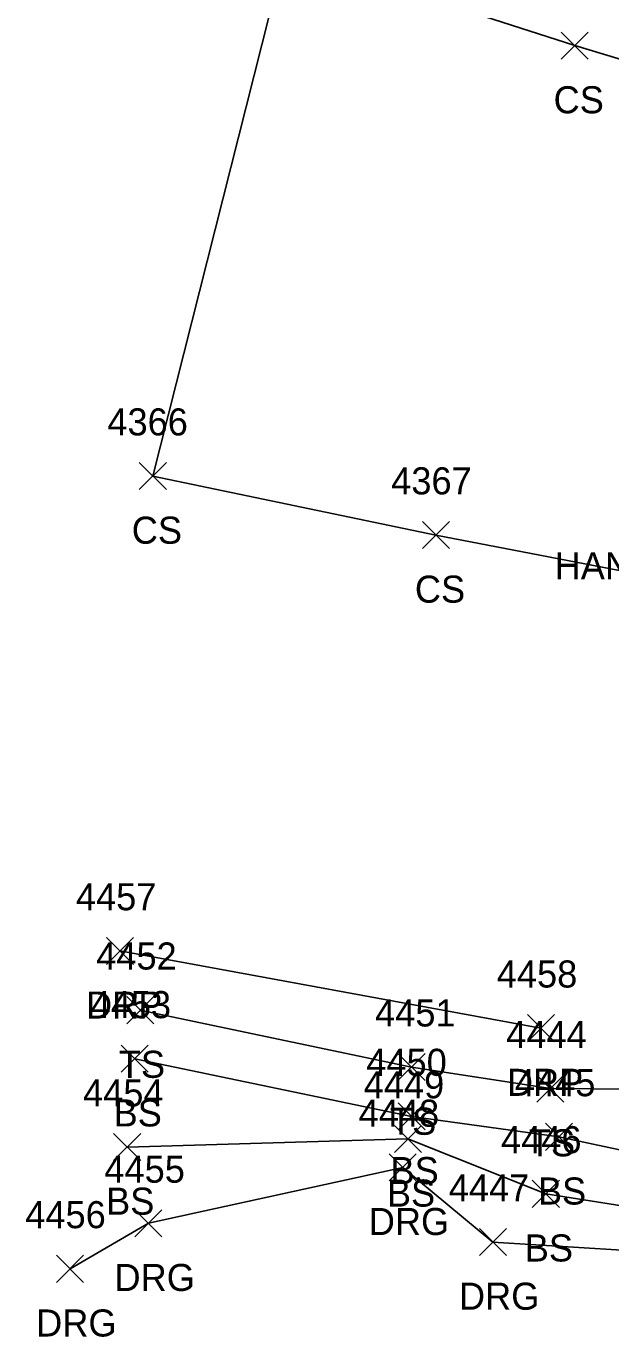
# Model space of a CAD drawing. Extents: x 1443912 to 1445411, y 621446 to 623693.
# Drawn here: x 1444840.5 to 1444883.7, y 623239.1 to 623335.6 of the extents above; entities that cross this region are included whole.
import ezdxf

# ---------------------------------------------------------------- set-up
doc = ezdxf.new("R2010")
doc.units = 0
for name, color, linetype in [('L_A', 7, 'Continuous'), ('L_I', 7, 'Continuous'), ('L_TIC', 7, 'Continuous'), ('LELB', 7, 'Continuous'), ('R_A', 7, 'Continuous'), ('R_I', 7, 'Continuous'), ('R_TIC', 7, 'Continuous'), ('RDG', 7, 'Continuous'), ('RDP', 7, 'Continuous'), ('S_C', 7, 'Continuous')]:
    doc.layers.add(name, color=color, linetype=linetype)

msp = doc.modelspace()

# ---------------------------------------------------------------- linework, layer by layer
at = {"layer": 'L_TIC'}
for points in [[(1444880.011, 623333.123), (1444882.011, 623335.123)], [(1444882.011, 623333.123), (1444880.011, 623335.123)], [(1444848.839, 623301.329), (1444850.839, 623303.329)], [(1444850.839, 623301.329), (1444848.839, 623303.329)], [(1444869.76, 623296.973), (1444871.76, 623298.973)], [(1444871.76, 623296.973), (1444869.76, 623298.973)], [(1444847.912, 623261.875), (1444849.912, 623263.875)], [(1444849.912, 623261.875), (1444847.912, 623263.875)], [(1444847.496, 623258.283), (1444849.496, 623260.283)], [(1444849.496, 623258.283), (1444847.496, 623260.283)], [(1444867.954, 623257.668), (1444869.954, 623259.668)], [(1444869.954, 623257.668), (1444867.954, 623259.668)], [(1444878.216, 623256.077), (1444880.216, 623258.077)], [(1444880.216, 623256.077), (1444878.216, 623258.077)], [(1444867.958, 623254.023), (1444869.958, 623256.023)], [(1444869.958, 623254.023), (1444867.958, 623256.023)], [(1444846.94, 623251.765), (1444848.94, 623253.765)], [(1444848.94, 623251.765), (1444846.94, 623253.765)], [(1444867.691, 623252.363), (1444869.691, 623254.363)], [(1444869.691, 623252.363), (1444867.691, 623254.363)], [(1444878.852, 623252.516), (1444880.852, 623254.516)], [(1444880.852, 623252.516), (1444878.852, 623254.516)], [(1444877.881, 623248.308), (1444879.881, 623250.308)], [(1444879.881, 623248.308), (1444877.881, 623250.308)]]:
    msp.add_lwpolyline(points, dxfattribs=at)
at = {"layer": 'LELB'}
for points in [[(1444899.838, 623328.442), (1444881.011, 623334.123), (1444859.605, 623341.032), (1444849.839, 623302.329), (1444870.76, 623297.973), (1444887.528, 623294.73)], [(1444904.831, 623326.954), (1444897.644, 623303.209), (1444893.476, 623290.997), (1444888.62, 623257.022), (1444879.216, 623257.077), (1444868.954, 623258.668), (1444848.912, 623262.875)], [(1444912.624, 623324.13), (1444916.045, 623308.663), (1444912.868, 623288.9), (1444897.071, 623253.248), (1444893.804, 623250.546), (1444891.827, 623247.272), (1444878.881, 623249.308), (1444868.691, 623253.363), (1444847.94, 623252.765)], [(1444893.804, 623250.546), (1444879.852, 623253.516), (1444868.958, 623255.023), (1444848.496, 623259.283)]]:
    msp.add_lwpolyline(points, dxfattribs=at)
at = {"layer": 'R_TIC'}
for points in [[(1444846.41, 623266.252), (1444848.41, 623268.252)], [(1444848.41, 623266.252), (1444846.41, 623268.252)], [(1444877.513, 623260.545), (1444879.513, 623262.545)], [(1444879.513, 623260.545), (1444877.513, 623262.545)], [(1444867.306, 623250.263), (1444869.306, 623252.263)], [(1444869.306, 623250.263), (1444867.306, 623252.263)], [(1444848.514, 623246.129), (1444850.514, 623248.129)], [(1444850.514, 623246.129), (1444848.514, 623248.129)], [(1444873.969, 623244.746), (1444875.969, 623246.746)], [(1444875.969, 623244.746), (1444873.969, 623246.746)], [(1444842.726, 623242.768), (1444844.726, 623244.768)], [(1444844.726, 623242.768), (1444842.726, 623244.768)]]:
    msp.add_lwpolyline(points, dxfattribs=at)
at = {"layer": 'RDG'}
msp.add_lwpolyline([(1444906.44, 623244.251), (1444894.039, 623244.548), (1444874.969, 623245.746), (1444868.306, 623251.263), (1444849.514, 623247.129), (1444843.726, 623243.768)], dxfattribs=at)
at = {"layer": 'RDP'}
msp.add_lwpolyline([(1444847.41, 623267.252), (1444878.513, 623261.545)], dxfattribs=at)

# ---------------------------------------------------------------- texts
at = {"layer": 'L_A'}
for s, p in [('CS', (1444879.452, 623329.123)), ('CS', (1444848.28, 623297.329)), ('CS', (1444869.201, 623292.973)), ('TS', (1444847.322, 623257.875)), ('BS', (1444846.937, 623254.283)), ('TS', (1444867.363, 623253.668)), ('TS', (1444877.625, 623252.077)), ('BS', (1444867.399, 623250.023)), ('BS', (1444867.132, 623248.363)), ('BS', (1444878.293, 623248.516)), ('BS', (1444846.381, 623247.765)), ('BS', (1444877.322, 623244.308))]:
    msp.add_text(s, height=2, dxfattribs=at).set_placement(p)
at = {"layer": 'L_I'}
for s, p in [('4366', (1444846.477, 623305.329)), ('4367', (1444867.453, 623300.973)), ('4452', (1444845.652, 623265.875)), ('4453', (1444845.237, 623262.283)), ('4451', (1444866.261, 623261.668)), ('4444', (1444875.956, 623260.077)), ('4450', (1444865.611, 623258.023)), ('4454', (1444844.68, 623255.765)), ('4449', (1444865.423, 623256.363)), ('4445', (1444876.592, 623256.516)), ('4446', (1444875.566, 623252.308))]:
    msp.add_text(s, height=2, dxfattribs=at).set_placement(p)
at = {"layer": 'R_A'}
for s, p in [('DRP', (1444844.899, 623262.252)), ('DRP', (1444876.001, 623256.545)), ('DRG', (1444865.794, 623246.263)), ('DRG', (1444847.003, 623242.129)), ('DRG', (1444872.457, 623240.746)), ('DRG', (1444841.214, 623238.768))]:
    msp.add_text(s, height=2, dxfattribs=at).set_placement(p)
at = {"layer": 'R_I'}
for s, p in [('4457', (1444844.151, 623270.252)), ('4458', (1444875.253, 623264.545)), ('4448', (1444865.046, 623254.263)), ('4455', (1444846.255, 623250.129)), ('4447', (1444871.709, 623248.746)), ('4456', (1444840.411, 623246.768))]:
    msp.add_text(s, height=2, dxfattribs=at).set_placement(p)
at = {"layer": 'S_C'}
msp.add_text('HANDICAP PARKING', height=2, dxfattribs=at).set_placement((1444879.53, 623294.69))

doc.saveas('drawing.dxf')
